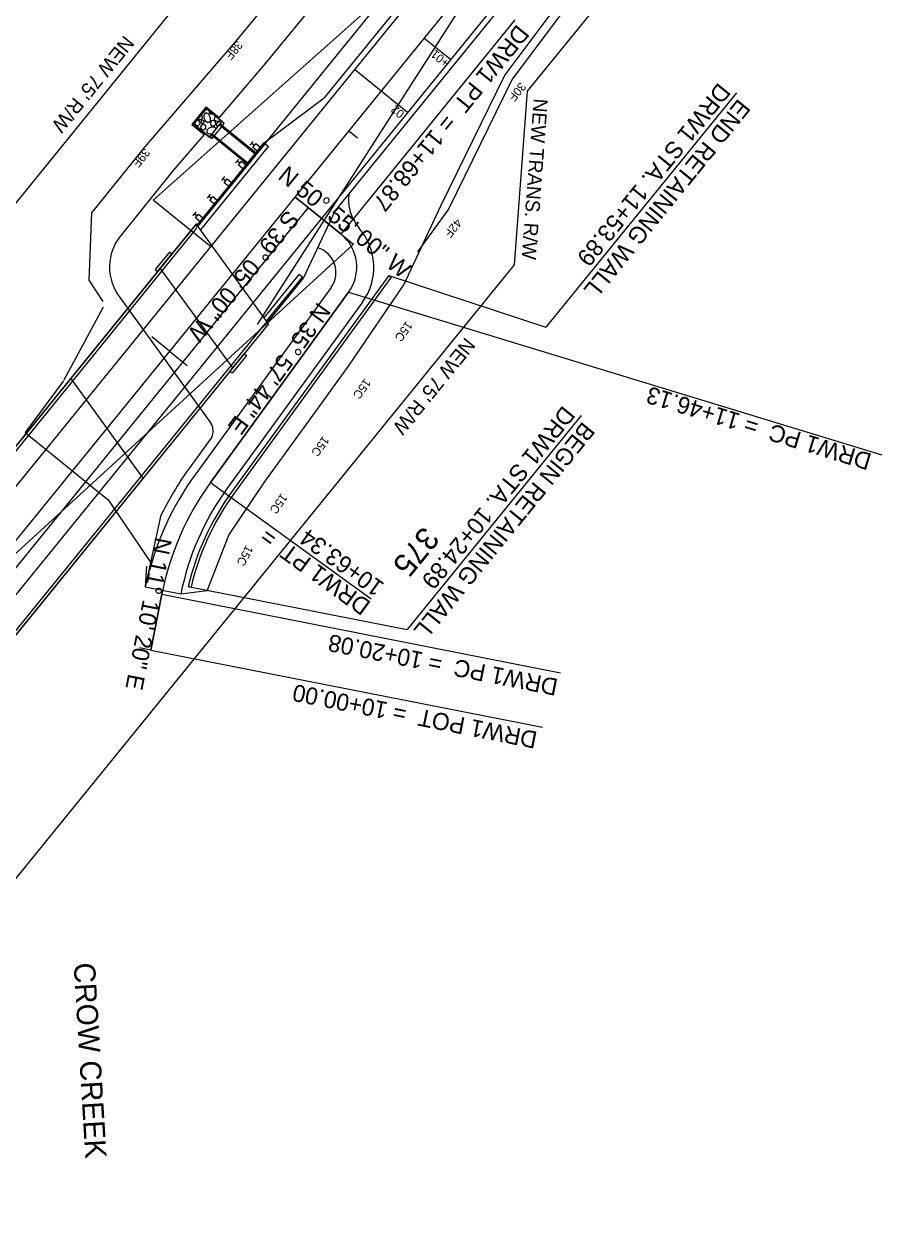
# Model space of a CAD drawing. Extents: x 144 to 1452322, y 4017 to 1128039.
# Drawn here: x 1450719.5 to 1451021.4, y 1126701.4 to 1127126.9 of the extents above; entities that cross this region are included whole.
import ezdxf

# ---------------------------------------------------------------- set-up
doc = ezdxf.new("R2010")
doc.units = 0
for name, color, linetype in [('BR_CONCRETE', 7, 'Continuous'), ('BR_PROPOSED_TRAVELWAY', 7, 'Continuous'), ('Default', 7, 'Continuous'), ('Drainage-Trench', 7, 'Continuous'), ('RD_GT_RetainingWall', 7, 'Continuous'), ('RD_HC_Cl', 7, 'Continuous'), ('RD_HC_CL_Rel', 7, 'Continuous'), ('RD_HC_Data', 7, 'Continuous'), ('RD_HC_Data_Rel', 7, 'Continuous'), ('RD_HC_Data_Tic', 7, 'Continuous'), ('RD_HC_Data_Tic_Rel', 7, 'Continuous'), ('RD_HC_TX_Sta50', 7, 'Continuous'), ('RD_PD_ALT1_TX', 7, 'Continuous'), ('RD_PD_BOC', 7, 'Continuous'), ('RD_PD_CstnLmt', 7, 'Continuous'), ('RD_PD_CstnLmt_TX', 7, 'Continuous'), ('RD_PD_DR_ErosCtrl', 7, 'Continuous'), ('RD_PD_DR_Inlet', 7, 'Continuous'), ('RD_PD_Driveway', 7, 'Continuous'), ('RD_PD_Driveway_TX', 7, 'Continuous'), ('RD_PD_EOP', 7, 'Continuous'), ('RD_PD_Final_TrvlWay', 7, 'Continuous'), ('RD_PD_Final_TX', 7, 'Continuous'), ('RD_PD_FOC', 7, 'Continuous'), ('RD_PD_GR', 7, 'Continuous'), ('RD_PD_PaveDit', 7, 'Continuous'), ('RD_PD_PaveShd', 7, 'Continuous'), ('RD_PD_RW', 7, 'Continuous'), ('RD_Sketch8', 7, 'Continuous'), ('RD_Sketch9', 7, 'Continuous')]:
    doc.layers.add(name, color=color, linetype=linetype)

# ---------------------------------------------------------------- blocks, each defined once
blk = doc.blocks.new('Guardrail_MTBBC3_Transition')
at = {"layer": 'RD_PD_GR'}
for p, q in [((37, 0.5), (0, 0.5)), ((0, 0.5), (0, 0)), ((0, 0), (37, 0)), ((3.525, 3.75), (1.775, 3.75)), ((1.775, 0.5), (1.775, 2.5)), ((1.775, 2.5), (3.525, 2.5)), ((3.525, 0.5), (1.775, 0.5)), ((2.65, 2.5), (2.65, 3.75)), ((3.525, 2.5), (3.525, 0.5)), ((11.525, 3.75), (9.775, 3.75)), ((9.775, 0.5), (9.775, 2.5)), ((9.775, 2.5), (11.525, 2.5)), ((11.525, 0.5), (9.775, 0.5)), ((10.65, 2.5), (10.65, 3.75)), ((11.525, 2.5), (11.525, 0.5)), ((19.525, 3.75), (17.775, 3.75)), ((17.775, 0.5), (17.775, 2.5)), ((17.775, 2.5), (19.525, 2.5)), ((19.525, 0.5), (17.775, 0.5)), ((18.65, 2.5), (18.65, 3.75)), ((19.525, 2.5), (19.525, 0.5)), ((27.525, 3.75), (25.775, 3.75)), ((25.775, 0.5), (25.775, 2.5)), ((25.775, 2.5), (27.525, 2.5)), ((27.525, 0.5), (25.775, 0.5)), ((26.65, 2.5), (26.65, 3.75)), ((27.525, 2.5), (27.525, 0.5)), ((30.65, 0.5), (30.65, 0)), ((35.525, 3.75), (33.775, 3.75)), ((33.775, 0.5), (33.775, 2.5)), ((33.775, 2.5), (35.525, 2.5)), ((35.525, 0.5), (33.775, 0.5)), ((34.65, 2.5), (34.65, 3.75)), ((35.525, 2.5), (35.525, 0.5)), ((37, 0), (37, 0.5))]:
    blk.add_line(p, q, dxfattribs=at)

msp = doc.modelspace()

# ---------------------------------------------------------------- linework, layer by layer
at = {"layer": 'BR_CONCRETE'}
for p, q in [((1450779.97, 1127056.48), (1450660.19, 1126908.99)), ((1450780.02, 1127056.41), (1450660.24, 1126908.92)), ((1450780.04, 1127054.84), (1450661.52, 1126908.91)), ((1450805.48, 1127021.26), (1450779.97, 1127056.48)), ((1450780.04, 1127054.84), (1450780.48, 1127055.78)), ((1450792.87, 1127005.74), (1450767.37, 1127040.95)), ((1450804.15, 1127021.34), (1450685.63, 1126875.41)), ((1450805.43, 1127021.33), (1450685.64, 1126873.85)), ((1450805.48, 1127021.26), (1450685.7, 1126873.78)), ((1450804.15, 1127021.34), (1450804.97, 1127021.96)), ((1450761.35, 1126966.93), (1450735.84, 1127002.14))]:
    msp.add_line(p, q, dxfattribs=at)
for points in [[(1450765.61, 1127040.38), (1450766.39, 1127039.75), (1450771.43, 1127045.96), (1450770.65, 1127046.59)], [(1450792.67, 1127003.9), (1450791.89, 1127004.53), (1450796.94, 1127010.74), (1450797.71, 1127010.11)]]:
    msp.add_lwpolyline(points, close=True, dxfattribs=at)
at = {"layer": 'BR_PROPOSED_TRAVELWAY'}
for p, q in [((1450785.44, 1127048.93), (1450665.65, 1126901.45)), ((1450800.02, 1127028.81), (1450680.23, 1126881.32))]:
    msp.add_line(p, q, dxfattribs=at)
at = {"layer": 'Default'}
msp.add_line((1450789.28, 1127091.11), (1450786.13, 1127087.23), dxfattribs=at)
at = {"layer": 'Drainage-Trench'}
for p, q in [((1450779.2, 1127091.57), (1450783.61, 1127097)), ((1450789.91, 1127091.89), (1450783.61, 1127097)), ((1450789.28, 1127091.11), (1450789.91, 1127091.89)), ((1450785.5, 1127086.45), (1450779.2, 1127091.57)), ((1450785.35, 1127087.86), (1450788.51, 1127091.74)), ((1450785.5, 1127086.45), (1450786.13, 1127087.23))]:
    msp.add_line(p, q, dxfattribs=at)
at = {"layer": 'RD_GT_RetainingWall'}
for p, q in [((1450847.84, 1127038.32), (1450792.36, 1126961.84)), ((1450848.65, 1127037.73), (1450793.17, 1126961.25)), ((1450847.84, 1127038.32), (1450848.65, 1127037.73)), ((1450778.2, 1126928.48), (1450777.23, 1126928.71))]:
    msp.add_line(p, q, dxfattribs=at)
for radius in [92, 91]:
    msp.add_arc((1450866.82, 1126907.81), radius, 144.0377, 166.873, dxfattribs=at)
at = {"layer": 'RD_HC_Cl'}
msp.add_line((1450930.04, 1127207.93), (1450648.85, 1126861.73), dxfattribs=at)
at = {"layer": 'RD_HC_CL_Rel'}
for p, q in [((1450831, 1127052.87), (1450814.79, 1127066.04)), ((1450785.07, 1126965.42), (1450833.68, 1127032.42)), ((1450764.01, 1126906.37), (1450767.9, 1126926.07))]:
    msp.add_line(p, q, dxfattribs=at)
for centre, radius, start, end in [((1450821.54, 1127041.23), 15, 324.0377, 50.9167), ((1450866.01, 1126906.69), 100, 144.0377, 168.8278)]:
    msp.add_arc(centre, radius, start, end, dxfattribs=at)
at = {"layer": 'RD_HC_Data_Rel'}
for p, q in [((1450831, 1127052.87), (1450892.33, 1127128.38)), ((1450833.68, 1127032.42), (1451021.39, 1126975.14)), ((1450785.07, 1126965.42), (1450841.65, 1126924.36)), ((1450767.9, 1126926.07), (1450908.28, 1126898.34)), ((1450764.01, 1126906.37), (1450901.93, 1126879.13))]:
    msp.add_line(p, q, dxfattribs=at)
at = {"layer": 'RD_HC_Data_Tic'}
for p, q in [((1450833.71, 1127089.32), (1450836.81, 1127086.8)), ((1450770.66, 1127011.7), (1450764.45, 1127016.74)), ((1450770.66, 1127011.7), (1450776.87, 1127006.66))]:
    msp.add_line(p, q, dxfattribs=at)
at = {"layer": 'RD_HC_Data_Tic_Rel'}
for p, q in [((1450806.59, 1126995.09), (1450804.17, 1126996.85)), ((1450764.01, 1126906.37), (1450760.09, 1126907.15))]:
    msp.add_line(p, q, dxfattribs=at)
at = {"layer": 'RD_PD_ALT1_TX'}
for p, q in [((1450869.5, 1127114.36), (1450860.19, 1127121.93)), ((1450854.37, 1127095.73), (1450835.74, 1127110.86))]:
    msp.add_line(p, q, dxfattribs=at)
at = {"layer": 'RD_PD_BOC'}
for p, q in [((1450780.33, 1127055.99), (1450803.57, 1127084.6)), ((1450799.5, 1127079.59), (1450803.91, 1127085.02)), ((1450780.33, 1127055.99), (1450799.5, 1127079.59)), ((1450805.13, 1127021.75), (1450817.82, 1127037.38))]:
    msp.add_line(p, q, dxfattribs=at)
at = {"layer": 'RD_PD_CstnLmt'}
for p, q in [((1450836.09, 1127151.8), (1450804.46, 1127113.08)), ((1450918.68, 1127149.14), (1450888.72, 1127109.06)), ((1450804.46, 1127113.08), (1450788.06, 1127094.03)), ((1450888.72, 1127109.06), (1450866.11, 1127063.01)), ((1450783.54, 1127097.71), (1450778.49, 1127091.5)), ((1450783.54, 1127097.71), (1450788.06, 1127094.03)), ((1450789.24, 1127092.43), (1450783.61, 1127097)), ((1450782.84, 1127087.97), (1450771.82, 1127075.17)), ((1450778.49, 1127091.5), (1450782.84, 1127087.97)), ((1450779.2, 1127091.57), (1450784.71, 1127087.1)), ((1450771.82, 1127075.17), (1450753.1, 1127051.95)), ((1450866.11, 1127063.01), (1450852.82, 1127034.7)), ((1450833.69, 1127006.31), (1450852.82, 1127034.7)), ((1450752.85, 1127030.89), (1450785.13, 1126986.33)), ((1450819.01, 1126986.08), (1450833.69, 1127006.31)), ((1450804.33, 1126965.84), (1450819.01, 1126986.08)), ((1450785.48, 1126981.31), (1450777.45, 1126970.25)), ((1450791.48, 1126946.85), (1450804.33, 1126965.84)), ((1450767.39, 1126953.36), (1450762.05, 1126928.53)), ((1450783.86, 1126927.16), (1450791.48, 1126946.85)), ((1450783.86, 1126927.16), (1450774.61, 1126926.03))]:
    msp.add_line(p, q, dxfattribs=at)
for centre, radius, start, end in [((1450767.15, 1127041.24), 17.65, 141.09, 215.9167), ((1450780.99, 1126983.52), 5, 333.7364, 34.1918), ((1450865.68, 1126906.24), 109, 144.0377, 154.385)]:
    msp.add_arc(centre, radius, start, end, dxfattribs=at)
at = {"layer": 'RD_PD_DR_ErosCtrl'}
for p, q in [((1450825.8, 1127159.76), (1450794.49, 1127121.44)), ((1450921.09, 1127147.35), (1450891.29, 1127107.49)), ((1450794.49, 1127121.44), (1450761.83, 1127083.49)), ((1450891.29, 1127107.49), (1450868.8, 1127061.69)), ((1450761.83, 1127083.49), (1450743.2, 1127060.38)), ((1450743.2, 1127060.38), (1450742.17, 1127036.67)), ((1450868.8, 1127061.69), (1450857.97, 1127046.64)), ((1450742.17, 1127036.67), (1450747.2, 1127029.18)), ((1450747.3, 1127027.11), (1450733.42, 1127001.47)), ((1450733.27, 1127001.23), (1450719.78, 1126983)), ((1450719.78, 1126983), (1450748.98, 1126959.28)), ((1450748.98, 1126959.28), (1450764.2, 1126937)), ((1450762.55, 1126935.87), (1450762.05, 1126928.53))]:
    msp.add_line(p, q, dxfattribs=at)
at = {"layer": 'RD_PD_DR_Inlet'}
for p, q in [((1450785.35, 1127087.86), (1450788.51, 1127091.74)), ((1450785.35, 1127087.86), (1450797.92, 1127077.65)), ((1450785.67, 1127088.25), (1450798.24, 1127078.04)), ((1450788.19, 1127091.35), (1450800.76, 1127081.14)), ((1450788.51, 1127091.74), (1450801.08, 1127081.53))]:
    msp.add_line(p, q, dxfattribs=at)
at = {"layer": 'RD_PD_Driveway'}
for p, q in [((1450827.51, 1127034.13), (1450779.88, 1126968.48)), ((1450838.54, 1127028.9), (1450790.74, 1126963.02)), ((1450774.61, 1126926.03), (1450762.05, 1126928.53))]:
    msp.add_line(p, q, dxfattribs=at)
for centre, radius, start, end in [((1450848.66, 1127064.91), 15, 170.8431, 221.1256), ((1450821.54, 1127041.23), 21, 324.0377, 41.1254), ((1450820.23, 1127039.42), 9, 324.0377, 73.3715), ((1450865.68, 1126906.24), 106, 144.0377, 167.8587), ((1450866.82, 1126907.81), 94, 144.0377, 168.8278)]:
    msp.add_arc(centre, radius, start, end, dxfattribs=at)
at = {"layer": 'RD_PD_Driveway_TX'}
for p, q in [((1450814.79, 1127066.04), (1450831, 1127052.87)), ((1450833.68, 1127032.42), (1450785.07, 1126965.42)), ((1450767.9, 1126926.07), (1450764.01, 1126906.37))]:
    msp.add_line(p, q, dxfattribs=at)
for centre, radius, start, end in [((1450821.54, 1127041.23), 15, 324.0377, 50.9167), ((1450866.01, 1126906.69), 100, 144.0377, 168.8278)]:
    msp.add_arc(centre, radius, start, end, dxfattribs=at)
at = {"layer": 'RD_PD_EOP'}
for p, q in [((1450781.54, 1127054.31), (1450805.46, 1127083.76)), ((1450803.91, 1127085.02), (1450805.46, 1127083.76)), ((1450803.91, 1127023.43), (1450816.27, 1127038.64)), ((1450817.82, 1127037.38), (1450816.27, 1127038.64))]:
    msp.add_line(p, q, dxfattribs=at)
at = {"layer": 'RD_PD_Final_TrvlWay'}
for p, q in [((1450918.96, 1127213.32), (1450785.44, 1127048.93)), ((1450939.35, 1127200.37), (1450800.02, 1127028.81))]:
    msp.add_line(p, q, dxfattribs=at)
at = {"layer": 'RD_PD_Final_TX'}
for p, q in [((1450970.25, 1127102.7), (1450903.13, 1127020.06)), ((1450847.84, 1127038.32), (1450903.13, 1127020.06)), ((1450915.49, 1126988.95), (1450854.27, 1126913.56)), ((1450777.23, 1126928.71), (1450854.27, 1126913.56))]:
    msp.add_line(p, q, dxfattribs=at)
at = {"layer": 'RD_PD_FOC'}
for p, q in [((1450780.63, 1127055.57), (1450804.3, 1127084.71)), ((1450804.82, 1127022.17), (1450817.43, 1127037.69))]:
    msp.add_line(p, q, dxfattribs=at)
at = {"layer": 'RD_PD_GR'}
msp.add_line((1450803.89, 1127084.34), (1450848.69, 1127139.5), dxfattribs=at)
at = {"layer": 'RD_PD_PaveDit'}
for p, q in [((1450784.99, 1127095.29), (1450785.78, 1127095.24)), ((1450788.22, 1127092.83), (1450788.53, 1127093.01)), ((1450785.58, 1127088.37), (1450785.93, 1127088.57)), ((1450787.53, 1127090.63), (1450787.6, 1127090.62))]:
    msp.add_line(p, q, dxfattribs=at)
for points in [[(1450783.23, 1127096.54), (1450783.5, 1127096.69), (1450783.68, 1127096.95)], [(1450784.54, 1127096.25), (1450784.58, 1127095.78), (1450784.99, 1127095.3)], [(1450779.56, 1127092.02), (1450779.6, 1127091.66), (1450780, 1127091.18)], [(1450780, 1127091.17), (1450780.88, 1127091.11), (1450781.42, 1127091.71), (1450781.32, 1127092.51), (1450780.64, 1127092.96), (1450780.26, 1127092.89)], [(1450780.69, 1127093.41), (1450780.79, 1127093.28)], [(1450780.79, 1127093.28), (1450781.67, 1127093.22), (1450782.21, 1127093.81), (1450782.11, 1127094.61), (1450781.82, 1127094.8)], [(1450781.98, 1127091.99), (1450782.5, 1127091.95), (1450782.83, 1127092.31), (1450782.77, 1127092.79), (1450782.36, 1127093.06), (1450781.98, 1127092.98), (1450781.7, 1127092.59), (1450781.73, 1127092.28), (1450781.98, 1127091.99)], [(1450784.97, 1127094.14), (1450784.47, 1127095.03), (1450783.75, 1127095.52), (1450783.19, 1127095.47), (1450782.75, 1127094.92), (1450782.73, 1127093.9), (1450783.18, 1127092.92), (1450783.88, 1127092.33), (1450784.5, 1127092.29), (1450785, 1127092.82), (1450785.08, 1127093.59), (1450784.95, 1127094.18)], [(1450785.46, 1127091.09), (1450786.33, 1127091.03), (1450786.88, 1127091.62), (1450786.78, 1127092.42), (1450786.1, 1127092.87), (1450785.46, 1127092.75), (1450785.01, 1127092.1), (1450785.05, 1127091.58), (1450785.46, 1127091.09)], [(1450786.81, 1127094.4), (1450786.41, 1127093.92), (1450786.37, 1127093.29), (1450786.9, 1127092.8), (1450787.66, 1127092.71), (1450788.26, 1127092.84)], [(1450788.92, 1127091.4), (1450788.85, 1127091.96), (1450788.17, 1127092.41), (1450787.53, 1127092.29), (1450787.08, 1127091.64), (1450787.12, 1127091.12), (1450787.53, 1127090.63)], [(1450782.02, 1127089.71), (1450782.9, 1127089.65), (1450783.44, 1127090.25), (1450783.35, 1127091.05), (1450782.66, 1127091.5), (1450782.03, 1127091.37), (1450781.57, 1127090.72), (1450781.62, 1127090.2), (1450782.02, 1127089.71)], [(1450786.93, 1127089.8), (1450786.91, 1127090.15), (1450786.35, 1127090.58), (1450785.34, 1127090.6), (1450784.35, 1127090.16), (1450783.77, 1127089.46), (1450783.73, 1127088.83), (1450784.26, 1127088.34), (1450785.02, 1127088.25), (1450785.62, 1127088.38)], [(1450785.52, 1127088.07), (1450785.18, 1127088), (1450784.91, 1127087.61), (1450784.94, 1127087.3), (1450785.18, 1127087.01)], [(1450785.18, 1127087.01), (1450785.71, 1127086.97), (1450786.02, 1127087.32)]]:
    msp.add_lwpolyline(points, dxfattribs=at)
at = {"layer": 'RD_PD_PaveShd'}
for p, q in [((1450917.41, 1127214.58), (1450825.07, 1127100.9)), ((1450940.91, 1127199.1), (1450829.02, 1127061.35)), ((1450803.91, 1127085.02), (1450825.07, 1127100.9)), ((1450817.82, 1127037.38), (1450829.02, 1127061.35))]:
    msp.add_line(p, q, dxfattribs=at)
at = {"layer": 'RD_PD_RW'}
for p, q in [((1450961.09, 1127182.71), (1450896.53, 1127103.23)), ((1450775.49, 1127136.61), (1450590.64, 1126909.01)), ((1450896.53, 1127103.23), (1450891.92, 1127042.04)), ((1450891.92, 1127042.04), (1450707.07, 1126814.44))]:
    msp.add_line(p, q, dxfattribs=at)
at = {"layer": 'RD_Sketch8'}
for p, q in [((1450764.89, 1127064.86), (1450885.94, 1127172.67)), ((1450888.34, 1127156.59), (1450801.44, 1127021.05)), ((1450785.07, 1127048.47), (1450764.89, 1127064.86))]:
    msp.add_line(p, q, dxfattribs=at)
at = {"layer": 'RD_Sketch9'}
for p, q in [((1450819.45, 1127062.25), (1450653.51, 1126857.94)), ((1450819.45, 1127062.25), (1450835.36, 1127049.33)), ((1450835.36, 1127049.33), (1450455.42, 1126701.38))]:
    msp.add_line(p, q, dxfattribs=at)

# ---------------------------------------------------------------- block references
at = {"layer": 'RD_PD_GR', "rotation": 50.91666489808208}
msp.add_blockref('Guardrail_MTBBC3_Transition', (1450780.57, 1127055.62), dxfattribs=at)

# ---------------------------------------------------------------- texts
at = {"layer": 'RD_HC_Data'}
for s, height, rotation, p in [('S 39%%d 05\' 00" W', 6, 230.9167, (1450812.09, 1127061.76)), ('CROW CREEK', 7.5, 273.4397, (1450736.87, 1126796))]:
    msp.add_text(s, height=height, rotation=rotation, dxfattribs=at).set_placement(p)
at = {"layer": 'RD_HC_Data_Rel'}
for s, rotation, p in [('DRW1 PT  = 11+68.87', 230.9167, (1450893.01, 1127127.09)), ('N 50%%d 55\' 00" W', 320.9167, (1450808.4, 1127072.65)), ('N 35%%d 57\' 44" E', 234.0377, (1450822.85, 1127029.24)), ('DRW1 PC  = 11+46.13', 163.0281, (1451018.19, 1126975.37)), ('DRW1 PT  = ', 144.0377, (1450841.88, 1126923.06)), ('10+63.34', 144.0377, (1450846.62, 1126929.6)), ('N 11%%d 10\' 20" E', 258.8278, (1450765.64, 1126946.37)), ('DRW1 PC  = 10+20.08', 168.8278, (1450907.71, 1126896.09)), ('DRW1 POT  = 10+00.00', 168.8278, (1450900.43, 1126877.47))]:
    msp.add_text(s, height=6, rotation=rotation, dxfattribs=at).set_placement(p)
at = {"layer": 'RD_HC_TX_Sta50'}
msp.add_text('375', height=8, rotation=230.9167, dxfattribs=at).set_placement((1450859.98, 1126950.36))
at = {"layer": 'RD_PD_ALT1_TX'}
for s, p in [('+01', (1450869.44, 1127113.78)), ('02', (1450853.57, 1127095.75))]:
    msp.add_text(s, height=3, rotation=140.9167, dxfattribs=at).set_placement(p)
at = {"layer": 'RD_PD_CstnLmt_TX'}
for s, rotation, p in [('38F', 230.9167, (1450794.36, 1127121.28)), ('30F', 230.9167, (1450894.09, 1127106.6)), ('39F', 230.9167, (1450761.73, 1127083.37)), ('42F', 230.9167, (1450871.54, 1127058.59)), ('15C', 234.0377, (1450854.04, 1127022.43)), ('15C', 234.0377, (1450839.36, 1127002.2)), ('15C', 234.0377, (1450824.68, 1126981.96)), ('15C', 234.0377, (1450810, 1126961.73)), ('15C', 241.6832, (1450797.64, 1126943.53))]:
    msp.add_text(s, height=3, rotation=rotation, dxfattribs=at).set_placement(p)
at = {"layer": 'RD_PD_Final_TX'}
for s, p in [('DRW1 STA. 11+53.89', (1450963.91, 1127106.56)), ('END RETAINING WALL', (1450970.9, 1127100.88)), ('DRW1 STA. 10+24.89', (1450909.16, 1126992.8)), ('BEGIN RETAINING WALL', (1450916.14, 1126987.13))]:
    msp.add_text(s, height=6, rotation=230.9167, dxfattribs=at).set_placement(p)
at = {"layer": 'RD_PD_RW'}
for s, rotation, p in [("NEW 75' R/W", 230.9167, (1450754.68, 1127123.2)), ('NEW TRANS. R/W', 265.6948, (1450898.85, 1127100.78)), ("NEW 75' R/W", 230.9167, (1450874.77, 1127016.8))]:
    msp.add_text(s, height=5, rotation=rotation, dxfattribs=at).set_placement(p)

doc.saveas('drawing.dxf')
